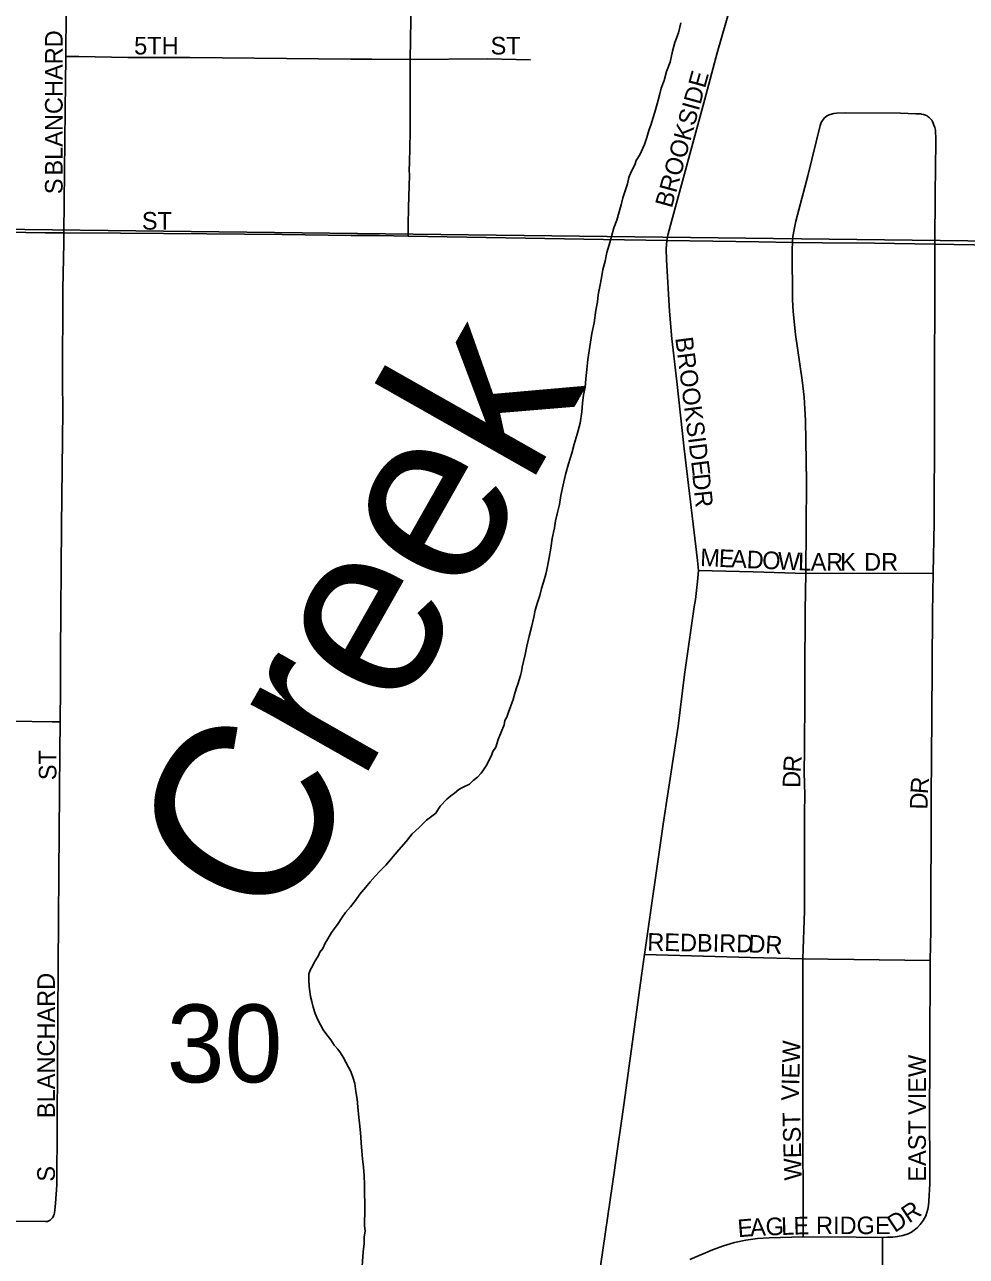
# Model space of a CAD drawing. Extents: x 0 to 68, y 0 to 52.9.
# Drawn here: x 43.794 to 44.462, y 39.851 to 40.725 of the extents above; entities that cross this region are included whole.
import ezdxf

# ---------------------------------------------------------------- set-up
doc = ezdxf.new("R2010")
doc.units = 0
for name, color, linetype in [('Default', 7, 'Continuous'), ('GM_X_Minor_River', 7, 'Continuous'), ('GM_X_Minor_River_Text', 7, 'Continuous'), ('GM_X_Township_Road', 7, 'Continuous')]:
    doc.layers.add(name, color=color, linetype=linetype)

msp = doc.modelspace()

# ---------------------------------------------------------------- linework, layer by layer
at = {"layer": 'Default'}
for points in [[(43.20282, 41.92092), (44.48328, 41.89508), (44.48288, 40.57177), (43.18329, 40.58736), (43.18298, 40.60237)], [(44.48288, 40.57177), (44.47349, 39.25009), (43.1609, 39.26536), (43.18329, 40.58736)]]:
    msp.add_lwpolyline(points, close=True, dxfattribs=at)
for points in [[(43.82281, 40.70282), (43.82344, 40.76727), (43.82339, 40.796), (43.82363, 40.81647), (43.82386, 40.82396)], [(44.06732, 40.70055), (44.06793, 40.74315), (44.06815, 40.76896), (44.06819, 40.77538), (44.0687, 40.79702)], [(44.24961, 40.57233), (44.25021, 40.57592), (44.25212, 40.58304), (44.27653, 40.67258), (44.28523, 40.70541), (44.29896, 40.75308)], [(43.82157, 40.57761), (43.82249, 40.66478), (43.82281, 40.70282)], [(43.82281, 40.70282), (43.83219, 40.70267), (43.86692, 40.70212), (43.89475, 40.70209), (43.91096, 40.70202), (44.02515, 40.70092), (44.04006, 40.70096), (44.06732, 40.70055)], [(44.06584, 40.57535), (44.06596, 40.58335), (44.06614, 40.59555), (44.06677, 40.61866), (44.06655, 40.62228), (44.06687, 40.62721), (44.06724, 40.64905), (44.06732, 40.70055)], [(44.06732, 40.70055), (44.12202, 40.70117), (44.14264, 40.70057), (44.15265, 40.70033)], [(44.43981, 40.56956), (44.43992, 40.6054), (44.4405, 40.64233), (44.44041, 40.64588), (44.4403, 40.64859), (44.44012, 40.65048), (44.43977, 40.65241), (44.43911, 40.65415), (44.43859, 40.65546), (44.43795, 40.65663), (44.43748, 40.65753), (44.43669, 40.65848), (44.43566, 40.6595), (44.43492, 40.66004), (44.43423, 40.66057), (44.433, 40.66121), (44.43164, 40.66162), (44.43029, 40.66195), (44.42965, 40.66203), (44.42805, 40.66213), (44.42613, 40.66213), (44.41531, 40.66249), (44.37659, 40.66288), (44.36995, 40.66259), (44.36794, 40.66235), (44.36543, 40.66172), (44.36343, 40.66084), (44.36152, 40.65932)], [(44.33876, 40.57084), (44.33904, 40.57508), (44.33977, 40.57997), (44.34095, 40.58584), (44.34965, 40.61816), (44.35829, 40.65374), (44.35914, 40.65598), (44.35991, 40.65739), (44.36075, 40.65842), (44.36152, 40.65932)], [(43.75345, 40.57856), (43.80836, 40.57769), (43.82157, 40.57761)], [(43.81891, 40.23062), (43.81924, 40.25459), (43.8192, 40.27924), (43.81974, 40.36947), (43.82068, 40.4515), (43.82056, 40.47204), (43.82089, 40.53767), (43.82147, 40.57045), (43.82157, 40.57761)], [(43.82157, 40.57761), (43.86163, 40.57737), (43.92309, 40.57689), (43.97638, 40.57659), (44.02553, 40.57571), (44.04566, 40.57569), (44.06584, 40.57535)], [(44.06584, 40.57535), (44.20445, 40.57287), (44.24961, 40.57233)], [(44.24961, 40.57233), (44.24912, 40.56637), (44.24922, 40.55848), (44.25143, 40.52211), (44.25297, 40.50242), (44.25651, 40.47226), (44.26187, 40.42435), (44.27129, 40.34521), (44.27191, 40.33803)], [(44.24961, 40.57233), (44.31483, 40.57117), (44.33876, 40.57084)], [(44.34821, 40.33598), (44.34866, 40.40117), (44.3479, 40.44457), (44.34692, 40.46093), (44.34559, 40.47314), (44.34093, 40.50561), (44.33919, 40.5219), (44.33881, 40.53008), (44.3385, 40.56574), (44.33876, 40.57084)], [(44.33876, 40.57084), (44.3599, 40.57054), (44.39679, 40.57036), (44.43981, 40.56956)], [(44.43853, 40.3361), (44.43917, 40.37206), (44.43945, 40.44184), (44.43981, 40.56956)], [(44.43981, 40.56956), (44.48113, 40.56884)], [(44.27191, 40.33803), (44.27121, 40.33013), (44.27066, 40.32386), (44.26983, 40.31743), (44.26901, 40.31215), (44.26214, 40.26415), (44.2576, 40.2277), (44.24693, 40.15799), (44.23369, 40.06546)], [(44.27191, 40.33803), (44.31089, 40.33699), (44.34821, 40.33598)], [(44.34611, 40.06255), (44.3472, 40.0966), (44.34721, 40.12528), (44.34721, 40.16627), (44.34743, 40.17856), (44.34709, 40.19491), (44.3471, 40.21131), (44.34747, 40.24812), (44.34734, 40.26451), (44.34766, 40.30958), (44.34821, 40.33598)], [(44.34821, 40.33598), (44.43853, 40.3361)], [(44.43642, 40.06135), (44.43684, 40.08255), (44.43723, 40.17691), (44.4376, 40.23433), (44.43803, 40.30782), (44.43853, 40.3361)], [(43.74973, 40.23173), (43.78457, 40.23109), (43.81322, 40.2307), (43.81891, 40.23062)], [(43.81261, 39.87772), (43.81338, 39.87859), (43.81385, 39.87939), (43.81419, 39.88018), (43.81455, 39.88132), (43.8148, 39.88231), (43.81507, 39.88424), (43.81554, 39.88915), (43.81644, 39.90179), (43.81704, 39.98796), (43.81771, 40.09053), (43.81788, 40.12333), (43.81861, 40.2095), (43.81891, 40.23062)], [(44.23369, 40.06546), (44.23181, 40.05238), (44.21901, 39.95894), (44.21267, 39.91441), (44.21262, 39.91408)], [(44.23369, 40.06546), (44.30893, 40.06351), (44.34611, 40.06255)], [(44.34626, 39.86529), (44.34599, 39.96137), (44.3461, 40.00645), (44.34611, 40.06255)], [(44.34611, 40.06255), (44.43642, 40.06135)], [(44.43549, 39.89052), (44.43612, 39.90275), (44.43609, 39.92326), (44.43587, 39.94386), (44.43614, 39.99687), (44.43642, 40.06135)], [(44.40252, 39.86476), (44.40609, 39.86488), (44.40987, 39.86509), (44.41334, 39.86546), (44.41695, 39.86615), (44.4207, 39.8674), (44.42319, 39.86865), (44.42513, 39.87004), (44.42749, 39.87184), (44.42943, 39.87406), (44.43151, 39.87684), (44.43322, 39.88015), (44.43414, 39.88253), (44.43484, 39.88475), (44.43525, 39.88738), (44.43549, 39.89052)], [(43.75253, 39.87808), (43.75341, 39.87748), (43.75469, 39.87695), (43.75576, 39.8767), (43.75699, 39.87659), (43.78463, 39.87624), (43.80854, 39.87606), (43.8098, 39.87619), (43.81083, 39.8765), (43.81183, 39.87708), (43.81261, 39.87772)], [(44.26588, 39.84925), (44.28191, 39.85608), (44.28969, 39.85883), (44.29761, 39.86111), (44.30567, 39.86285), (44.31383, 39.864), (44.32205, 39.86462), (44.34626, 39.86529)], [(44.34626, 39.86529), (44.38399, 39.86506), (44.40252, 39.86476)], [(44.40304, 39.75274), (44.40279, 39.78662), (44.40277, 39.8071), (44.40252, 39.86476)]]:
    msp.add_lwpolyline(points, dxfattribs=at)
at = {"layer": 'GM_X_Minor_River'}
for points in [[(44.25941, 40.72659), (44.25776, 40.7196), (44.25511, 40.71263), (44.25348, 40.70665), (44.25182, 40.69865), (44.24918, 40.69219), (44.24754, 40.6857), (44.24542, 40.68023), (44.24432, 40.67524), (44.24269, 40.66925), (44.24107, 40.66326), (44.23947, 40.65878), (44.23839, 40.65479), (44.23679, 40.65031), (44.23519, 40.64533), (44.23358, 40.64034), (44.23042, 40.63289), (44.22783, 40.62893), (44.22677, 40.62594), (44.22416, 40.62098), (44.22257, 40.617), (44.22148, 40.6125), (44.21987, 40.60752), (44.21827, 40.60254), (44.21716, 40.59755), (44.21555, 40.59256), (44.21393, 40.58658), (44.21181, 40.5811), (44.21018, 40.57512), (44.20856, 40.56913), (44.20694, 40.56365), (44.20582, 40.55765), (44.20419, 40.55167), (44.20307, 40.54567), (44.20194, 40.53968), (44.20082, 40.53368), (44.20021, 40.52868), (44.19909, 40.52268), (44.1979, 40.51368), (44.19625, 40.50619), (44.19336, 40.48769), (44.19272, 40.48068), (44.19209, 40.47417), (44.19146, 40.46817), (44.19035, 40.46268), (44.18972, 40.45667), (44.1891, 40.45067), (44.18793, 40.44266), (44.18577, 40.43468), (44.18362, 40.4277), (44.18198, 40.42122), (44.17982, 40.41374), (44.17766, 40.40626), (44.17601, 40.39877), (44.17435, 40.39128), (44.17322, 40.38478), (44.17158, 40.3783), (44.17048, 40.37331), (44.16987, 40.3683), (44.16822, 40.36081), (44.16707, 40.35382), (44.16594, 40.34732), (44.1648, 40.34082), (44.16369, 40.33533), (44.16207, 40.32984), (44.16047, 40.32536), (44.15937, 40.32037), (44.15776, 40.31539), (44.15615, 40.3099)], [(44.15615, 40.3099), (44.15504, 40.30491), (44.1534, 40.29792), (44.15176, 40.29143), (44.15011, 40.28445), (44.14899, 40.27845), (44.14788, 40.27346), (44.1468, 40.26947), (44.14624, 40.26647), (44.14567, 40.26347), (44.14461, 40.26048), (44.14406, 40.25799), (44.14247, 40.25401), (44.14139, 40.25002), (44.14032, 40.24653), (44.13872, 40.24205), (44.13712, 40.23756), (44.13605, 40.23408), (44.13449, 40.2316), (44.13393, 40.2286), (44.12971, 40.21816), (44.12809, 40.21267), (44.12602, 40.2097), (44.12496, 40.20672), (44.12339, 40.20374), (44.12182, 40.20026), (44.11975, 40.19729), (44.11769, 40.19433), (44.11512, 40.19137), (44.11206, 40.18892), (44.1095, 40.18647), (44.10443, 40.18406), (44.1019, 40.18261), (44.09884, 40.18016), (44.09629, 40.17821), (44.09323, 40.17576), (44.08861, 40.17084), (44.0855, 40.16588), (44.07888, 40.161), (44.07376, 40.15559), (44.06865, 40.15118), (44.06453, 40.14575), (44.05939, 40.13983), (44.05014, 40.12899), (44.04605, 40.12505), (44.04246, 40.12112), (44.03887, 40.11717), (44.03578, 40.11323), (44.03166, 40.10829), (44.02856, 40.10384), (44.02496, 40.0994), (44.02137, 40.09546), (44.01878, 40.0915), (44.01619, 40.08754), (44.01361, 40.08408), (44.01155, 40.08112), (44.00895, 40.07665), (44.00688, 40.07369), (44.00529, 40.06971), (44.00324, 40.06724), (44.00219, 40.06475), (43.99907, 40.0598), (43.99802, 40.05732), (43.99647, 40.05484), (43.9954, 40.05185), (43.99531, 40.04734), (43.99572, 40.04282), (43.99615, 40.0393), (43.99658, 40.03578), (43.99751, 40.03225), (43.99844, 40.02822), (43.99985, 40.02368), (44.00176, 40.01912), (44.0037, 40.01557), (44.00563, 40.01203), (44.00807, 40.00847), (44.011, 40.0049), (44.01344, 40.00134), (44.01589, 39.99828), (44.01784, 39.99573), (44.01979, 39.99268), (44.02172, 39.98913), (44.02366, 39.98558), (44.0251, 39.98254), (44.02652, 39.97851), (44.02794, 39.97396), (44.02883, 39.96843), (44.02972, 39.96289), (44.03011, 39.95737), (44.03096, 39.94983), (44.03138, 39.94581), (44.03179, 39.94129), (44.03219, 39.93626), (44.0326, 39.93174), (44.03299, 39.92622), (44.03338, 39.92069), (44.03426, 39.91466), (44.03464, 39.90863), (44.03501, 39.9021), (44.03488, 39.89559), (44.03526, 39.88956)], [(44.03526, 39.88956), (44.03517, 39.88555), (44.03508, 39.88104), (44.035, 39.87703), (44.03492, 39.87302), (44.03535, 39.8695), (44.03476, 39.865), (44.03467, 39.86049), (44.03404, 39.85448), (44.03269, 39.83745)]]:
    msp.add_lwpolyline(points, dxfattribs=at)
at = {"layer": 'GM_X_Township_Road'}
msp.add_lwpolyline([(44.21262, 39.91408), (44.20235, 39.84441)], dxfattribs=at)

# ---------------------------------------------------------------- texts
at = {"layer": 'Default'}
for s, height, rotation, p in [('BLANCHARD', 0.0125, 90, (43.82065, 40.61827)), ('5TH', 0.0125, 0.00001, (43.8714, 40.70422)), ('ST', 0.0125, 0.00001, (44.1244, 40.70422)), ('BROOKSIDE', 0.0125, 74.55378, (44.25303, 40.5947)), ('S', 0.0125, 90, (43.82065, 40.60507)), ('ST', 0.0125, 0.00001, (43.8769, 40.57993)), ('BROOKSIDE', 0.0125, 277.30463, (44.25543, 40.50307)), ('DR', 0.0125, 276.0168, (44.26753, 40.40622)), ('M', 0.0125, 357.48592, (44.273, 40.34122)), ('E', 0.0125, 357.49083, (44.28619, 40.34064)), ('A', 0.0125, 357.48576, (44.29498, 40.34026)), ('D', 0.0125, 357.49331, (44.30597, 40.33977)), ('O', 0.0125, 357.48576, (44.31696, 40.33929)), ('W', 0.0125, 357.47759, (44.32795, 40.33881)), ('L', 0.0125, 358.58833, (44.3425, 40.33817)), ('A', 0.0125, 359.89125, (44.35161, 40.33795)), ('R', 0.0125, 359.99406, (44.36264, 40.33792)), ('K', 0.0125, 359.99285, (44.37254, 40.33792)), ('DR', 0.0125, 0.00001, (44.3895, 40.33792)), ('ST', 0.0125, 90, (43.81625, 40.18927)), ('R', 0.0125, 85.42994, (44.34441, 40.19451)), ('D', 0.0125, 89.08194, (44.34425, 40.18372)), ('R', 0.0125, 85.47835, (44.43473, 40.17911)), ('D', 0.0125, 88.49198, (44.43445, 40.16829)), ('REDBIRD', 0.0125, 359.0577, (44.23554, 40.06827)), ('DR', 0.0125, 356.98902, (44.30711, 40.06716)), ('BLANCHARD', 0.0125, 90, (43.81515, 39.94947)), ('30', 0.05525, 0.00001, (43.8945, 39.97485)), ('VIEW', 0.0125, 88.45263, (44.34315, 39.96163)), ('VIEW', 0.0125, 90, (44.43335, 39.95167)), ('WEST', 0.0125, 91.50669, (44.34534, 39.90541)), ('EAST', 0.0125, 90, (44.43335, 39.90437)), ('S', 0.0125, 90, (43.81515, 39.90437)), ('DR', 0.0125, 33.69679, (44.4113, 39.86783)), ('E', 0.0125, 4.65018, (44.30019, 39.86491)), ('A', 0.0125, 2.99556, (44.30887, 39.86562)), ('G', 0.0125, 1.74895, (44.31978, 39.86619)), ('L', 0.0125, 1.66701, (44.33077, 39.86653)), ('E', 0.0125, 1.68905, (44.33957, 39.86679)), ('RIDGE', 0.0125, 0.00001, (44.3554, 39.86712))]:
    msp.add_text(s, height=height, rotation=rotation, dxfattribs=at).set_placement(p)
at = {"layer": 'GM_X_Minor_River_Text'}
msp.add_text('Creek', height=0.125054, rotation=60.46201, dxfattribs=at).set_placement((43.97246, 40.08089))

doc.saveas('drawing.dxf')
